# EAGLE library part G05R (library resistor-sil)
SIL RESISTOR
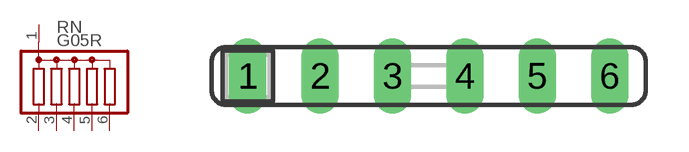
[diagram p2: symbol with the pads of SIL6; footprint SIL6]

Designator prefix RN

## G05R (OC_FARNELL: unknown; OC_NEWARK: unknown)  [SIL6]
1  1  pas
2  2  pas
3  3  pas
4  4  pas
5  5  pas
6  6  pas

## Footprint SIL6 (pad centres in mm)
Single In Line
drill 0.813 long: 1 -6.35,0; 2 -3.81,0; 3 -1.27,0; 4 1.27,0; 5 3.81,0; 6 6.35,0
